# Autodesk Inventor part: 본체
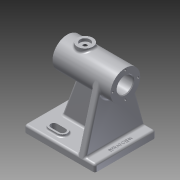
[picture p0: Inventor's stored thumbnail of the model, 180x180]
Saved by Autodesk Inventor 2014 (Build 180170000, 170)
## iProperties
Created: 2019-10
Part Number: 본체
Material: Aluminum 6061
Document SubType Name: Modeling
Designer: kh
Density: 2.71 g/cm^3
Appearance: Aluminum - Flat
Mass: 588.008 g
Surface Area: 541.312 cm^2
Volume: 216.977 cm^3
Author: kh
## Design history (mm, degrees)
sketch "Sketch1"
  geometry: L1 (-50, -43)-(50, -43); L2 (50, -43)-(50, 43); L3 (50, 43)-(-50, 43); L4 (-50, 43)-(-50, -43); L5 (-50, -43)-(50, 43); L6 (50, -43)-(-50, 43); 1 further point
  constraints: 12 end point, 2 midpoint, 2 parallel, 1 horizontal, 1 perpendicular
  dimensions: "d0" = 100 distance of L3.end L2.end; "d1" = 86 distance of L2.end L1.end
extrude "Extrusion1" new body sketch "Sketch1" distance "d2" = 10; taper "d3" = 0 deg
sketch "Sketch2"
  geometry: L1 (-32, 107)-(-32, 86); L2 (-32, 86)-(50, 86); L3 (-32, 107)-(50, 107); L4 (50, 107)-(50, 86); 2 further points
  constraints: 8 end point, 2 perpendicular, 1 parallel, 1 vertical, 1 vertical alignment
  dimensions: "d5" = 86 distance of point (50, 0) L2.end; "d7" = 82 distance of L1.start L3.end; "d8" = 42 diameter of L3 L2
revolve "Revolution1" sketch "Sketch2" stored, may be unused: angle "d9" = 90 deg
sketch "Sketch3"
  geometry: L1 (-32, 65)-(-32, 107) reference; L2 (50, 65)-(50, 107) reference; L3 (-32, 86)-(-32, 100.5); L4 (-32, 100.5)-(30, 100.5); L5 (30, 100.5)-(30, 86); L6 (30, 97.5)-(50, 97.5); L7 (50, 86)-(50, 97.5); L8 (-32, 86)-(50, 86); 1 further point
  constraints: 12 end point, 4 point on line, 3 perpendicular, 2 midpoint, 1 collinear
  dimensions: "d10" = 20 distance of L6.start L6.end; "d13" = 62 distance of L3.end L4.end; "d14" = 23 diameter of L6 L8; "d15" = 29 diameter of L4 L8
revolve "Revolution2" sketch "Sketch3" stored, may be unused: angle "d16" = 90 deg
sketch "Sketch4"
  geometry: C1 r 21 at (0, 0) reference; A1 r 18 centre (0, 0) between (0, 18) and (18, 0); 3 further points
  constraints: 4 point on circle, 2 horizontal alignment, 2 vertical alignment, 1 centre point, 1 coincident
  dimensions: "d17" = 36 diameter of A1
hole "Hole1" sketch "Sketch4" at (0, 18), (18, 0), (0, -18), (-18, 0) diameter "d18" = 2.621; stored, may be unused: countersink angle "d22" = 90 deg, drill point angle "d24" = 118 deg; dims "d19" = 8, "d20" = 4, "d21" = 2, "d23" = 10
workplane "Work Plane1"
mirror "Mirror1"
workplane "Work Plane2"
fillet "Fillet1" dims "d47" = 3
workplane "Work Plane3"
sketch "Sketch9"
  geometry: L1 (-24, 27)-(-12, 27); L2 (-24, 20)-(-12, 20); L3 (-12, 34)-(-24, 34); L4 (-50, 43)-(-50, -43) reference; L5 (0, 0)-(-50, 0); L6 (-12, -34)-(-24, -34); L7 (-24, -20)-(-12, -20); L8 (-24, -27)-(-12, -27); A1 r 7 centre (-24, 27) between (-24, 34) and (-24, 20); A2 r 7 centre (-12, 27) between (-12, 20) and (-12, 34); A3 r 7 centre (-24, -27) between (-24, -20) and (-24, -34); A4 r 7 centre (-12, -27) between (-12, -34) and (-12, -20); 2 further points
  constraints: 18 end point, 8 point on circle, 7 symmetric about line, 4 centre point, 4 tangent, 2 midpoint, 1 horizontal, 1 parallel, 2 other
  dimensions: "d41" = 12 distance of L1.start L1.end; "d42" = 26 distance from line of L1.start L4; "d43" = 7 radius of A1; "d44" = 54 distance of point (-18, -27) point (-18, 27)
extrude "Extrusion2" join sketch "Sketch9" stored distance "d45" = 3; taper "d46" = 0 deg
workplane "Work Plane4"
sketch "Sketch10"
  geometry: L1 (0, 10)-(80, 10) reference; L2 (0, 0)-(80, 0) reference; L3 (-2.896, 7.783)-(19.728, 91.48); L4 (60.272, 91.48)-(82.896, 7.783); L5 (-2.896, 7.783)-(82.896, 7.783); A1 r 3 centre (0, 7) between (0, 10) and (-3, 7) reference; A2 r 3 centre (80, 7) between (83, 7) and (80, 10) reference; A3 r 21 centre (40, 86) between (19.728, 91.48) and (60.272, 91.48) reference; 2 further points
  constraints: 6 end point, 4 point on circle, 4 tangent, 1 midpoint, 1 parallel
feature "Rib3" sketch "Sketch10" dims "d50" = 1, "d51" = 10, "d52" = 0, "d53" = 0, "d54" = 1, "d55" = 1
sketch "Sketch12"
  geometry: L1 (-14.708, 65.751)-(-35, 10); L2 (-47, 10)-(25, 10) reference; L3 (-50, 0)-(-50, 7) reference; 1 further point
  constraints: 2 end point, 1 horizontal alignment
  dimensions: "d56" = 70 deg angle of L2 L1; "d57" = 15 distance from line of L1.end L3
feature "Rib4" sketch "Sketch12" dims "d58" = 1, "d59" = 10, "d60" = 0, "d61" = 0, "d62" = 1, "d63" = 1
sketch "Sketch13"
  geometry: L1 (-24, 27)-(-12, 27); L2 (-24, 22.5)-(-12, 22.5); L3 (-12, 31.5)-(-24, 31.5); L4 (-24, 34)-(-12, 34) reference; L5 (-12, 20)-(-24, 20) reference; A1 r 4.5 centre (-24, 27) between (-24, 31.5) and (-24, 22.5); A2 r 4.5 centre (-12, 27) between (-12, 22.5) and (-12, 31.5); A3 r 7 centre (-12, 27) between (-12, 20) and (-12, 34) reference; A4 r 7 centre (-24, 27) between (-24, 34) and (-24, 20) reference; 2 further points
  constraints: 8 end point, 4 point on circle, 4 tangent, 2 centre point, 1 coincident, 1 horizontal, 1 midpoint, 1 parallel
  dimensions: "d64" = 12 distance of L1.start L1.end; "d65" = 4.5 radius of A2
extrude "Extrusion3" cut sketch "Sketch13" stored distance "d66" = 10; taper "d67" = 0 deg
mirror "Mirror2"
workplane "Work Plane6"
  workplane "Work Plane5"
sketch "Sketch14"
  geometry: L1 (41, 21)-(41, -21) reference; C1 r 11 at (16, 0); 1 further point
  constraints: 1 centre point, 1 horizontal alignment
  dimensions: "d69" = 22 diameter of C1; "d70" = 25 distance from line of L1 C1.centre
extrude "Extrusion4" join sketch "Sketch14" stored distance "d73" = 10; taper "d74" = 0 deg
sketch "Sketch15"
  geometry: C1 r 11 at (0, 0) reference; 2 further points
  constraints: 1 coincident
hole "Hole2" sketch "Sketch15" at (0, 0) diameter "d75" = 5.242; stored, may be unused: countersink angle "d79" = 90 deg, drill point angle "d81" = 118 deg; dims "d76" = 8, "d77" = 14, "d78" = 4, "d80" = 10
chamfer "Chamfer1" distance "d82" = 1; stored, may be unused: second distance "d83" = 2, angle "d84" = 45 deg
fillet "Fillet2" dims "d85" = 3
fillet "Fillet3" dims "d86" = 3
fillet "Fillet4" dims "d87" = 3
fillet "Fillet5" dims "d88" = 3
sketch "Sketch16"
  geometry: L1 (50, -40)-(50, 40) reference; L2 (-47, -43)-(47, -43) reference; 1 further point
  constraints: 1 other
  dimensions: "d89" = 7 distance from line of point (43, 0) L1; "d90" = 43 distance from line of L2 point (43, 0)
extrude "Extrusion5" join sketch "Sketch16" distance "d91" = 0.5; taper "d92" = 0 deg
fillet "Fillet6" dims "d93" = 2
body "Solid1"
node "Projected Loop1"
other parameters: "d25" = -15, "d40" = 3, "d48" = -15, "d68" = 3
